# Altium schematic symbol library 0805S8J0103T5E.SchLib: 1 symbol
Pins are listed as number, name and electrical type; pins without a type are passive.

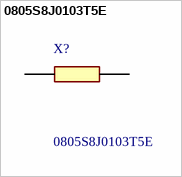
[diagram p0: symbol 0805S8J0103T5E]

## 0805S8J0103T5E
designator X?
THICK FILM CHIP RESISTORS Ordering Procedure: (Ex.: 1206, 1/4W-S, 5%, 1.2, T/R-5000); Manufacturer_Name: ROYALOHM; Geometry.Height: 0.65mm
footprint RESC2013X65N
pins: 1, 2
